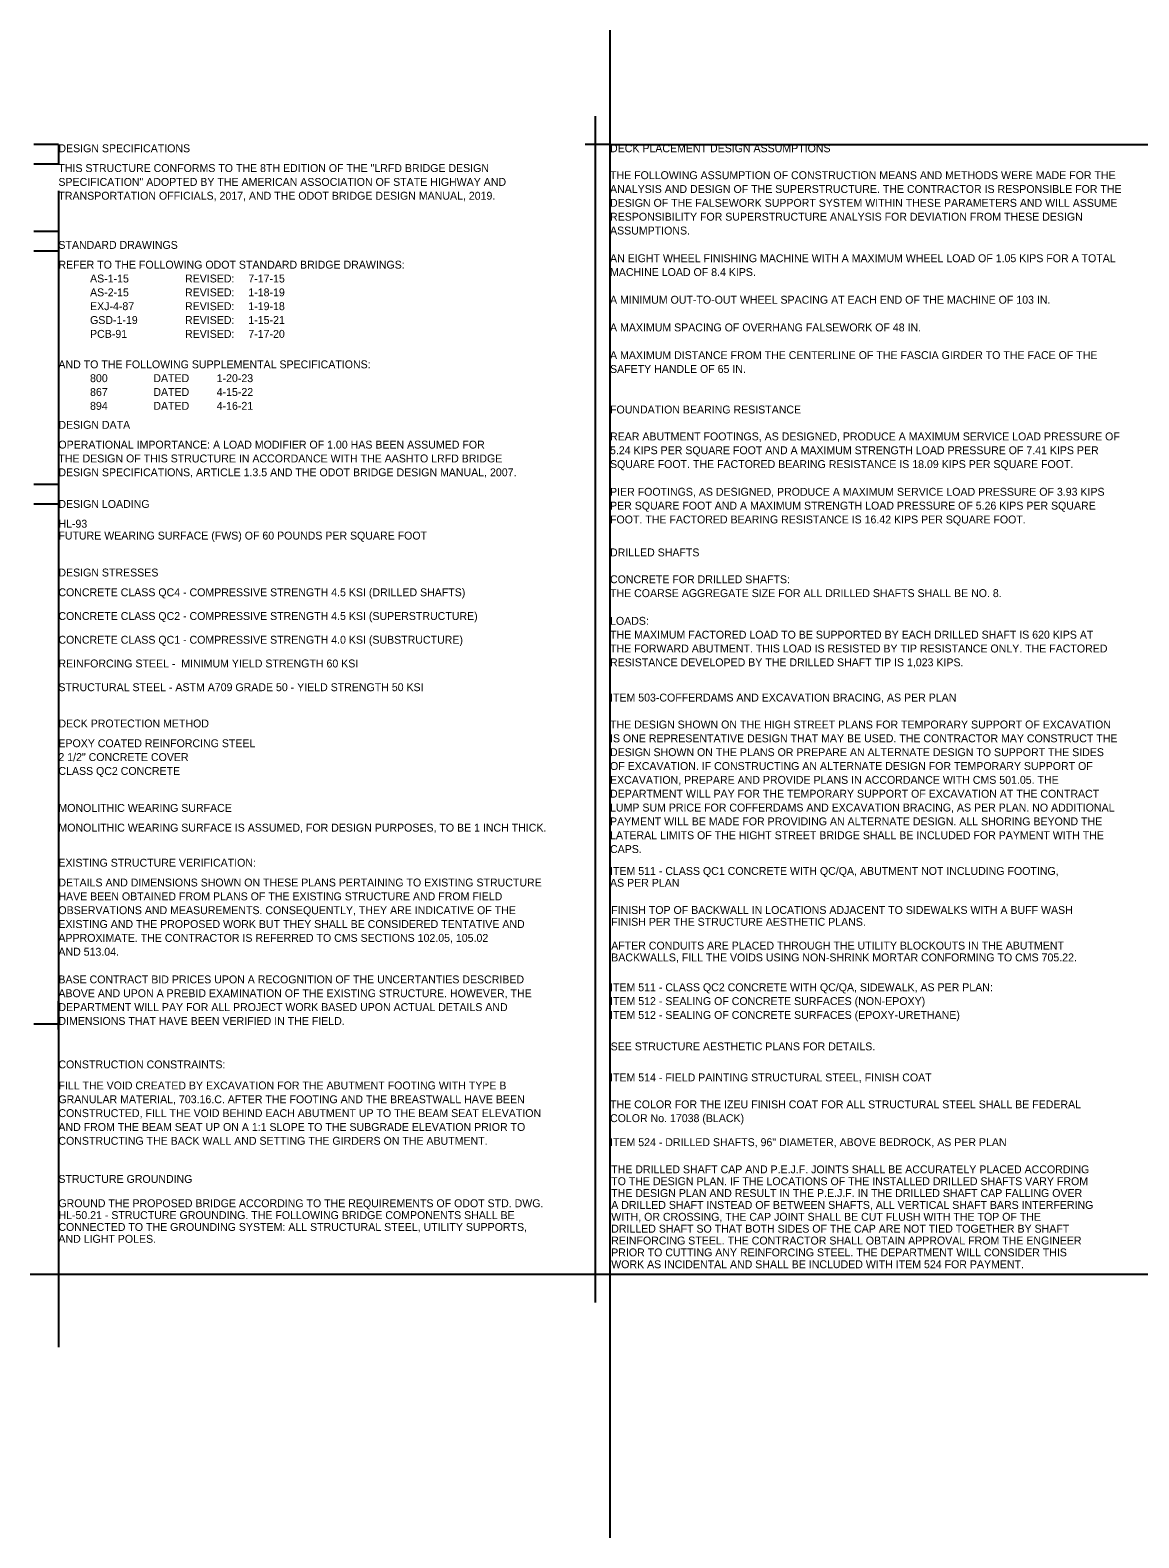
# Model space of a CAD drawing. Extents: x 29 to 1530617, y 1 to 675368.
# Drawn here: x 1530555.19 to 1530574.8, y 675321.19 to 675347.87 of the extents above; entities that cross this region are included whole.
import ezdxf

# ---------------------------------------------------------------- set-up
doc = ezdxf.new("R2010")
doc.units = 0
for name, color, linetype in [('BR_P_Gen_Text', 7, 'Continuous'), ('SC_Scratch1', 7, 'Continuous'), ('SC_Scratch2', 7, 'Continuous'), ('SC_Scratch3', 7, 'Continuous')]:
    doc.layers.add(name, color=color, linetype=linetype)

msp = doc.modelspace()

# ---------------------------------------------------------------- linework, layer by layer
at = {"layer": 'SC_Scratch1'}
for p, q in [((1530555.688, 675345.853), (1530555.688, 675345.503)), ((1530555.688, 675345.031), (1530555.688, 675324.562)), ((1530555.688, 675344.873), (1530555.688, 675344.313))]:
    msp.add_line(p, q, dxfattribs=at)
at = {"layer": 'SC_Scratch2'}
for p, q in [((1530555.688, 675345.853), (1530555.252, 675345.853)), ((1530565.447, 675345.853), (1530565.01, 675345.853)), ((1530555.688, 675345.503), (1530555.252, 675345.503)), ((1530555.688, 675344.313), (1530555.252, 675344.313)), ((1530555.688, 675343.963), (1530555.252, 675343.963)), ((1530555.688, 675339.833), (1530555.252, 675339.833)), ((1530555.688, 675339.483), (1530555.252, 675339.483)), ((1530555.688, 675330.281), (1530555.252, 675330.281))]:
    msp.add_line(p, q, dxfattribs=at)
at = {"layer": 'SC_Scratch3'}
for p, q in [((1530565.447, 675321.188), (1530565.447, 675347.874)), ((1530565.188, 675325.353), (1530565.188, 675346.353)), ((1530565.447, 675345.853), (1530586.537, 675345.853)), ((1530555.688, 675330.188), (1530555.688, 675330.688)), ((1530555.188, 675325.853), (1530585.688, 675325.853))]:
    msp.add_line(p, q, dxfattribs=at)

# ---------------------------------------------------------------- texts
at = {"layer": 'BR_P_Gen_Text'}
for s, p in [('DESIGN SPECIFICATIONS', (1530555.688, 675345.713)), ('DECK PLACEMENT DESIGN ASSUMPTIONS', (1530565.447, 675345.713)), ('THIS STRUCTURE CONFORMS TO THE 8TH EDITION OF THE "LRFD BRIDGE DESIGN', (1530555.688, 675345.363)), ('SPECIFICATION" ADOPTED BY THE AMERICAN ASSOCIATION OF STATE HIGHWAY AND', (1530555.688, 675345.118)), ('THE FOLLOWING ASSUMPTION OF CONSTRUCTION MEANS AND METHODS WERE MADE FOR THE ', (1530565.447, 675345.237)), ('TRANSPORTATION OFFICIALS, 2017, AND THE ODOT BRIDGE DESIGN MANUAL, 2019.', (1530555.688, 675344.873)), ('ANALYSIS AND DESIGN OF THE SUPERSTRUCTURE. THE CONTRACTOR IS RESPONSIBLE FOR THE ', (1530565.447, 675344.992)), ('DESIGN OF THE FALSEWORK SUPPORT SYSTEM WITHIN THESE PARAMETERS AND WILL ASSUME ', (1530565.447, 675344.747)), ('RESPONSIBILITY FOR SUPERSTRUCTURE ANALYSIS FOR DEVIATION FROM THESE DESIGN ', (1530565.447, 675344.502)), ('ASSUMPTIONS. ', (1530565.447, 675344.257)), ('STANDARD DRAWINGS ', (1530555.688, 675344.003)), ('REFER TO THE FOLLOWING ODOT STANDARD BRIDGE DRAWINGS:', (1530555.688, 675343.653)), ('AN EIGHT WHEEL FINISHING MACHINE WITH A MAXIMUM WHEEL LOAD OF 1.05 KIPS FOR A TOTAL ', (1530565.447, 675343.767)), ('MACHINE LOAD OF 8.4 KIPS.', (1530565.447, 675343.522)), ('AS-1-15  ', (1530556.248, 675343.408)), ('REVISED:', (1530557.928, 675343.408)), ('7-17-15', (1530559.048, 675343.408)), ('AS-2-15', (1530556.248, 675343.163)), ('REVISED:', (1530557.928, 675343.163)), ('1-18-19', (1530559.048, 675343.163)), ('A MINIMUM OUT-TO-OUT WHEEL SPACING AT EACH END OF THE MACHINE OF 103 IN.', (1530565.447, 675343.032)), ('EXJ-4-87', (1530556.248, 675342.918)), ('REVISED:', (1530557.928, 675342.918)), ('1-19-18', (1530559.048, 675342.918)), ('GSD-1-19', (1530556.248, 675342.673)), ('REVISED:', (1530557.928, 675342.673)), ('1-15-21', (1530559.048, 675342.673)), ('A MAXIMUM SPACING OF OVERHANG FALSEWORK OF 48 IN.', (1530565.447, 675342.542)), ('PCB-91', (1530556.248, 675342.428)), ('REVISED:', (1530557.928, 675342.428)), ('7-17-20', (1530559.048, 675342.428)), ('A MAXIMUM DISTANCE FROM THE CENTERLINE OF THE FASCIA GIRDER TO THE FACE OF THE ', (1530565.447, 675342.052)), ('AND TO THE FOLLOWING SUPPLEMENTAL SPECIFICATIONS:', (1530555.688, 675341.889)), ('SAFETY HANDLE OF 65 IN.', (1530565.447, 675341.807)), ('800', (1530556.248, 675341.644)), ('867', (1530556.248, 675341.399)), ('DATED', (1530557.368, 675341.644)), ('DATED', (1530557.368, 675341.399)), ('4-15-22', (1530558.488, 675341.399)), ('1-20-23', (1530558.488, 675341.644)), ('894 ', (1530556.248, 675341.154)), ('DATED ', (1530557.368, 675341.154)), ('4-16-21', (1530558.488, 675341.154)), ('FOUNDATION BEARING RESISTANCE', (1530565.447, 675341.089)), ('DESIGN DATA', (1530555.688, 675340.818)), ('REAR ABUTMENT FOOTINGS, AS DESIGNED, PRODUCE A MAXIMUM SERVICE LOAD PRESSURE OF ', (1530565.447, 675340.613)), ('OPERATIONAL IMPORTANCE: A LOAD MODIFIER OF 1.00 HAS BEEN ASSUMED FOR', (1530555.688, 675340.468)), ('5.24 KIPS PER SQUARE FOOT AND A MAXIMUM STRENGTH LOAD PRESSURE OF 7.41 KIPS PER ', (1530565.447, 675340.368)), ('THE DESIGN OF THIS STRUCTURE IN ACCORDANCE WITH THE AASHTO LRFD BRIDGE', (1530555.688, 675340.223)), ('SQUARE FOOT. THE FACTORED BEARING RESISTANCE IS 18.09 KIPS PER SQUARE FOOT.', (1530565.447, 675340.123)), ('DESIGN SPECIFICATIONS, ARTICLE 1.3.5 AND THE ODOT BRIDGE DESIGN MANUAL, 2007.', (1530555.688, 675339.978)), ('PIER FOOTINGS, AS DESIGNED, PRODUCE A MAXIMUM SERVICE LOAD PRESSURE OF 3.93 KIPS ', (1530565.447, 675339.633)), ('DESIGN LOADING', (1530555.688, 675339.418)), ('PER SQUARE FOOT AND A MAXIMUM STRENGTH LOAD PRESSURE OF 5.26 KIPS PER SQUARE ', (1530565.447, 675339.388)), ('HL-93', (1530555.688, 675339.068)), ('FOOT. THE FACTORED BEARING RESISTANCE IS 16.42 KIPS PER SQUARE FOOT.', (1530565.447, 675339.143)), ('FUTURE WEARING SURFACE (FWS) OF 60 POUNDS PER SQUARE FOOT', (1530555.688, 675338.858)), ('DRILLED SHAFTS', (1530565.447, 675338.56)), ('DESIGN STRESSES', (1530555.688, 675338.204)), ('CONCRETE FOR DRILLED SHAFTS:', (1530565.447, 675338.084)), ('CONCRETE CLASS QC4 - COMPRESSIVE STRENGTH 4.5 KSI (DRILLED SHAFTS)', (1530555.688, 675337.854)), ('THE COARSE AGGREGATE SIZE FOR ALL DRILLED SHAFTS SHALL BE NO. 8.', (1530565.447, 675337.839)), ('CONCRETE CLASS QC2 - COMPRESSIVE STRENGTH 4.5 KSI (SUPERSTRUCTURE)', (1530555.688, 675337.434)), ('LOADS:', (1530565.447, 675337.349)), ('CONCRETE CLASS QC1 - COMPRESSIVE STRENGTH 4.0 KSI (SUBSTRUCTURE)', (1530555.688, 675337.014)), ('THE MAXIMUM FACTORED LOAD TO BE SUPPORTED BY EACH DRILLED SHAFT IS 620 KIPS AT ', (1530565.447, 675337.104)), ('THE FORWARD ABUTMENT. THIS LOAD IS RESISTED BY TIP RESISTANCE ONLY. THE FACTORED ', (1530565.447, 675336.859)), ('REINFORCING STEEL -  MINIMUM YIELD STRENGTH 60 KSI', (1530555.688, 675336.594)), ('RESISTANCE DEVELOPED BY THE DRILLED SHAFT TIP IS 1,023 KIPS.', (1530565.447, 675336.614)), ('STRUCTURAL STEEL - ASTM A709 GRADE 50 - YIELD STRENGTH 50 KSI', (1530555.688, 675336.174)), ('ITEM 503-COFFERDAMS AND EXCAVATION BRACING, AS PER PLAN', (1530565.447, 675335.991)), ('DECK PROTECTION METHOD', (1530555.688, 675335.532)), ('THE DESIGN SHOWN ON THE HIGH STREET PLANS FOR TEMPORARY SUPPORT OF EXCAVATION ', (1530565.447, 675335.514)), ('IS ONE REPRESENTATIVE DESIGN THAT MAY BE USED. THE CONTRACTOR MAY CONSTRUCT THE ', (1530565.447, 675335.269)), ('EPOXY COATED REINFORCING STEEL', (1530555.688, 675335.182)), ('DESIGN SHOWN ON THE PLANS OR PREPARE AN ALTERNATE DESIGN TO SUPPORT THE SIDES ', (1530565.447, 675335.024)), ('2 1/2" CONCRETE COVER', (1530555.688, 675334.937)), ('OF EXCAVATION. IF CONSTRUCTING AN ALTERNATE DESIGN FOR TEMPORARY SUPPORT OF ', (1530565.447, 675334.779)), ('CLASS QC2 CONCRETE', (1530555.688, 675334.692)), ('EXCAVATION, PREPARE AND PROVIDE PLANS IN ACCORDANCE WITH CMS 501.05. THE ', (1530565.447, 675334.534)), ('DEPARTMENT WILL PAY FOR THE TEMPORARY SUPPORT OF EXCAVATION AT THE CONTRACT ', (1530565.447, 675334.289)), ('MONOLITHIC WEARING SURFACE', (1530555.688, 675334.038)), ('LUMP SUM PRICE FOR COFFERDAMS AND EXCAVATION BRACING, AS PER PLAN. NO ADDITIONAL ', (1530565.447, 675334.044)), ('MONOLITHIC WEARING SURFACE IS ASSUMED, FOR DESIGN PURPOSES, TO BE 1 INCH THICK.', (1530555.688, 675333.688)), ('PAYMENT WILL BE MADE FOR PROVIDING AN ALTERNATE DESIGN. ALL SHORING BEYOND THE ', (1530565.447, 675333.799)), ('LATERAL LIMITS OF THE HIGHT STREET BRIDGE SHALL BE INCLUDED FOR PAYMENT WITH THE ', (1530565.447, 675333.554)), ('CAPS.', (1530565.447, 675333.309)), ('EXISTING STRUCTURE VERIFICATION:', (1530555.688, 675333.067)), ('ITEM 511 - CLASS QC1 CONCRETE WITH QC/QA, ABUTMENT NOT INCLUDING FOOTING, ', (1530565.447, 675332.922)), ('DETAILS AND DIMENSIONS SHOWN ON THESE PLANS PERTAINING TO EXISTING STRUCTURE ', (1530555.688, 675332.717)), ('AS PER PLAN', (1530565.447, 675332.712)), ('HAVE BEEN OBTAINED FROM PLANS OF THE EXISTING STRUCTURE AND FROM FIELD ', (1530555.688, 675332.472)), ('OBSERVATIONS AND MEASUREMENTS. CONSEQUENTLY, THEY ARE INDICATIVE OF THE', (1530555.688, 675332.227)), ('FINISH TOP OF BACKWALL IN LOCATIONS ADJACENT TO SIDEWALKS WITH A BUFF WASH ', (1530565.468, 675332.231)), ('EXISTING AND THE PROPOSED WORK BUT THEY SHALL BE CONSIDERED TENTATIVE AND', (1530555.688, 675331.982)), ('FINISH PER THE STRUCTURE AESTHETIC PLANS.', (1530565.468, 675332.021)), ('APPROXIMATE. THE CONTRACTOR IS REFERRED TO CMS SECTIONS 102.05, 105.02', (1530555.688, 675331.737)), ('AFTER CONDUITS ARE PLACED THROUGH THE UTILITY BLOCKOUTS IN THE ABUTMENT ', (1530565.468, 675331.601)), ('AND 513.04.', (1530555.688, 675331.492)), ('BACKWALLS, FILL THE VOIDS USING NON-SHRINK MORTAR CONFORMING TO CMS 705.22.', (1530565.468, 675331.391)), ('BASE CONTRACT BID PRICES UPON A RECOGNITION OF THE UNCERTANTIES DESCRIBED', (1530555.688, 675331.002)), ('ABOVE AND UPON A PREBID EXAMINATION OF THE EXISTING STRUCTURE. HOWEVER, THE', (1530555.688, 675330.757)), ('ITEM 511 - CLASS QC2 CONCRETE WITH QC/QA, SIDEWALK, AS PER PLAN:', (1530565.447, 675330.863)), ('DEPARTMENT WILL PAY FOR ALL PROJECT WORK BASED UPON ACTUAL DETAILS AND', (1530555.688, 675330.512)), ('ITEM 512 - SEALING OF CONCRETE SURFACES (NON-EPOXY)', (1530565.447, 675330.618)), ('DIMENSIONS THAT HAVE BEEN VERIFIED IN THE FIELD.', (1530555.688, 675330.267)), ('ITEM 512 - SEALING OF CONCRETE SURFACES (EPOXY-URETHANE)', (1530565.447, 675330.373)), ('SEE STRUCTURE AESTHETIC PLANS FOR DETAILS.', (1530565.458, 675329.816)), ('CONSTRUCTION CONSTRAINTS:', (1530555.688, 675329.498)), ('FILL THE VOID CREATED BY EXCAVATION FOR THE ABUTMENT FOOTING WITH TYPE B ', (1530555.688, 675329.125)), ('ITEM 514 - FIELD PAINTING STRUCTURAL STEEL, FINISH COAT', (1530565.447, 675329.267)), ('GRANULAR MATERIAL, 703.16.C. AFTER THE FOOTING AND THE BREASTWALL HAVE BEEN ', (1530555.688, 675328.88)), ('CONSTRUCTED, FILL THE VOID BEHIND EACH ABUTMENT UP TO THE BEAM SEAT ELEVATION ', (1530555.688, 675328.635)), ('THE COLOR FOR THE IZEU FINISH COAT FOR ALL STRUCTURAL STEEL SHALL BE FEDERAL ', (1530565.447, 675328.791)), ('AND FROM THE BEAM SEAT UP ON A 1:1 SLOPE TO THE SUBGRADE ELEVATION PRIOR TO ', (1530555.688, 675328.39)), ('COLOR No. 17038 (BLACK)', (1530565.447, 675328.546)), ('CONSTRUCTING THE BACK WALL AND SETTING THE GIRDERS ON THE ABUTMENT.', (1530555.688, 675328.145)), ('ITEM 524 - DRILLED SHAFTS, 96" DIAMETER, ABOVE BEDROCK, AS PER PLAN', (1530565.447, 675328.121)), ('THE DRILLED SHAFT CAP AND P.E.J.F. JOINTS SHALL BE ACCURATELY PLACED ACCORDING ', (1530565.468, 675327.64)), ('STRUCTURE GROUNDING', (1530555.688, 675327.47)), ('TO THE DESIGN PLAN. IF THE LOCATIONS OF THE INSTALLED DRILLED SHAFTS VARY FROM ', (1530565.468, 675327.43)), ('GROUND THE PROPOSED BRIDGE ACCORDING TO THE REQUIREMENTS OF ODOT STD. DWG. ', (1530555.688, 675327.04)), ('A DRILLED SHAFT INSTEAD OF BETWEEN SHAFTS, ALL VERTICAL SHAFT BARS INTERFERING ', (1530565.468, 675327.01)), ('THE DESIGN PLAN AND RESULT IN THE P.E.J.F. IN THE DRILLED SHAFT CAP FALLING OVER ', (1530565.468, 675327.22)), ('HL-50.21 - STRUCTURE GROUNDING. THE FOLLOWING BRIDGE COMPONENTS SHALL BE ', (1530555.688, 675326.83)), ('WITH, OR CROSSING, THE CAP JOINT SHALL BE CUT FLUSH WITH THE TOP OF THE ', (1530565.468, 675326.8)), ('CONNECTED TO THE GROUNDING SYSTEM: ALL STRUCTURAL STEEL, UTILITY SUPPORTS, ', (1530555.688, 675326.62)), ('DRILLED SHAFT SO THAT BOTH SIDES OF THE CAP ARE NOT TIED TOGETHER BY SHAFT ', (1530565.468, 675326.59)), ('AND LIGHT POLES.', (1530555.688, 675326.41)), ('REINFORCING STEEL. THE CONTRACTOR SHALL OBTAIN APPROVAL FROM THE ENGINEER ', (1530565.468, 675326.38)), ('WORK AS INCIDENTAL AND SHALL BE INCLUDED WITH ITEM 524 FOR PAYMENT.', (1530565.468, 675325.96)), ('PRIOR TO CUTTING ANY REINFORCING STEEL. THE DEPARTMENT WILL CONSIDER THIS ', (1530565.468, 675326.17))]:
    msp.add_text(s, height=0.14, dxfattribs=at).set_placement(p)

doc.saveas('drawing.dxf')
